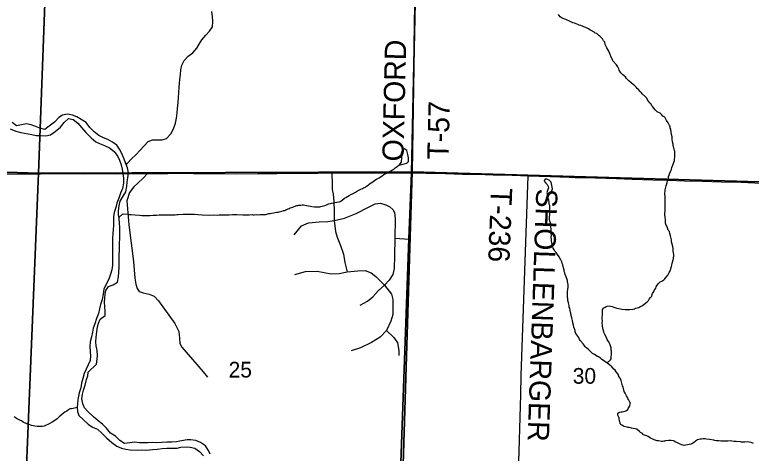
# Model space of a CAD drawing. Extents: x 0 to 34, y 0 to 22.
# Drawn here: x 5.004 to 6.971, y 18.962 to 20.132 of the extents above; entities that cross this region are included whole.
import ezdxf

# ---------------------------------------------------------------- set-up
doc = ezdxf.new("R2010")
doc.units = 0
for name, color, linetype in [('Default', 7, 'Continuous'), ('GM_X_Major_River', 7, 'Continuous'), ('GM_X_Minor_River', 7, 'Continuous'), ('GM_X_Section', 7, 'Continuous'), ('GM_X_Section_Text', 7, 'Continuous'), ('GM_X_State_Route', 7, 'Continuous'), ('GM_X_Township_Road', 7, 'Continuous'), ('GM_X_Township_Road_Text', 7, 'Continuous')]:
    doc.layers.add(name, color=color, linetype=linetype)

msp = doc.modelspace()

# ---------------------------------------------------------------- linework, layer by layer
at = {"layer": 'Default'}
msp.add_lwpolyline([(4.98, 17.7015), (5.0396, 17.6997), (5.1253, 17.6972), (5.2207, 17.6942), (5.2737, 17.6923), (5.3125, 17.691), (5.4195, 17.6873), (5.5532, 17.6849), (5.9893, 17.6676), (6.0568, 19.5343), (6.0632, 19.7108), (6.0696, 20.0002), (6.0777, 20.3704), (6.08, 20.4768), (6.0809, 20.5156), (6.0839, 20.7194), (6.0871, 20.9), (2.1, 20.9)], dxfattribs=at)
msp.add_lwpolyline([(8.9, 17.6104), (8.9, 20.9), (6.0871, 20.9), (6.0839, 20.7194), (6.0809, 20.5156), (6.08, 20.4768), (6.0777, 20.3704), (6.0696, 20.0002), (6.0632, 19.7108), (6.0568, 19.5343), (5.9893, 17.6676), (6.9889, 17.643), (7.0308, 17.6406), (8.0065, 17.6245)], close=True, dxfattribs=at)
at = {"layer": 'GM_X_Major_River'}
for points in [[(5.2835, 19.6225), (5.2857, 19.635), (5.2941, 19.648), (5.3009, 19.66), (5.3035, 19.6736), (5.3046, 19.6861), (5.3061, 19.6967), (5.3076, 19.7107), (5.3053, 19.7237), (5.2996, 19.7371), (5.2961, 19.7471), (5.2918, 19.7574), (5.2854, 19.7705), (5.277, 19.784), (5.2655, 19.7927), (5.2527, 19.7995), (5.2411, 19.804), (5.2284, 19.8101), (5.2161, 19.8195), (5.205, 19.8312), (5.1948, 19.8444), (5.1821, 19.8531), (5.1698, 19.8599), (5.1581, 19.8644), (5.1453, 19.867), (5.1315, 19.864), (5.1219, 19.8582), (5.1101, 19.846), (5.0965, 19.8349), (5.0849, 19.8262), (5.0709, 19.8296), (5.0578, 19.8349), (5.048, 19.8382), (5.0359, 19.8408), (5.0092, 19.8362), (4.9973, 19.8445)], [(4.9923, 19.8283), (5.0073, 19.8215), (5.0205, 19.8181), (5.0303, 19.8159), (5.0401, 19.8145), (5.05, 19.8127), (5.0617, 19.8105), (5.0749, 19.8097), (5.0875, 19.8094), (5.1001, 19.8117), (5.1125, 19.8208), (5.1261, 19.8326), (5.1359, 19.8449), (5.148, 19.8559), (5.1604, 19.8529), (5.1731, 19.8431), (5.183, 19.8318), (5.194, 19.8178), (5.2081, 19.8042), (5.2211, 19.7935), (5.2308, 19.7883), (5.244, 19.7838), (5.2571, 19.777), (5.2697, 19.7672), (5.2796, 19.7536), (5.2842, 19.744), (5.2888, 19.7321), (5.2915, 19.7199), (5.2931, 19.7088), (5.2943, 19.6962), (5.2947, 19.6826), (5.292, 19.6686), (5.2867, 19.6558), (5.2818, 19.6427), (5.2769, 19.6299), (5.2739, 19.6182), (5.2697, 19.6047), (5.2678, 19.5926), (5.2683, 19.5804), (5.2676, 19.5706), (5.2673, 19.5581)], [(5.2005, 19.1783), (5.2223, 19.1994), (5.2246, 19.2134), (5.2252, 19.2229), (5.2241, 19.2362), (5.2214, 19.2488), (5.2205, 19.2591), (5.2213, 19.272), (5.2236, 19.2859), (5.2254, 19.2992), (5.2276, 19.3094), (5.2321, 19.3195), (5.2453, 19.3294), (5.2456, 19.3396), (5.2448, 19.3537), (5.2444, 19.3643), (5.2447, 19.3757), (5.2457, 19.3867), (5.2475, 19.3965), (5.2543, 19.4069), (5.2669, 19.4115), (5.2789, 19.4188), (5.2812, 19.4332), (5.2819, 19.4453), (5.2831, 19.4582), (5.2834, 19.4703), (5.2833, 19.4802), (5.2832, 19.4912), (5.2836, 19.5029), (5.2844, 19.5181), (5.285, 19.5397), (5.2846, 19.553), (5.2845, 19.5652), (5.2841, 19.5758), (5.2833, 19.588), (5.2817, 19.599), (5.2816, 19.6089), (5.2835, 19.6225)], [(5.2673, 19.5581), (5.2666, 19.5486), (5.2651, 19.5357), (5.2651, 19.5217), (5.2652, 19.5122), (5.2652, 19.4989), (5.2652, 19.486), (5.2657, 19.4765), (5.2654, 19.4643), (5.2635, 19.4519), (5.2601, 19.4398), (5.2556, 19.427), (5.2484, 19.4132), (5.2419, 19.4001), (5.24, 19.3865), (5.2374, 19.3721), (5.2332, 19.3593), (5.2302, 19.3472), (5.2276, 19.3352), (5.223, 19.3213), (5.2181, 19.3073), (5.214, 19.2961), (5.2122, 19.2855), (5.2091, 19.2723), (5.2057, 19.2595), (5.2046, 19.2466), (5.2058, 19.2337), (5.2069, 19.2215), (5.2059, 19.2097), (5.1894, 19.1747)], [(5.1894, 19.1747), (5.1858, 19.1614), (5.1829, 19.1493), (5.1807, 19.1364), (5.1767, 19.1236), (5.1738, 19.1096), (5.172, 19.0956), (5.1714, 19.0838), (5.1716, 19.0732), (5.1756, 19.0625), (5.1875, 19.0509), (5.2002, 19.0393), (5.2122, 19.0318), (5.225, 19.0259), (5.237, 19.0158), (5.2504, 19.0023), (5.2635, 18.9907), (5.2773, 18.9805), (5.2897, 18.9758), (5.3011, 18.9729), (5.3124, 18.9708), (5.3322, 18.9705), (5.342, 18.9707), (5.3542, 18.9705), (5.3637, 18.9707), (5.3732, 18.9716), (5.3849, 18.973), (5.3979, 18.9746), (5.41, 18.9752), (5.4233, 18.9753), (5.4381, 18.9758), (5.448, 18.9783), (5.4629, 18.9792), (5.4727, 18.9779), (5.4848, 18.9754), (5.4975, 18.9668), (5.5083, 18.9552)], [(5.5259, 18.9595), (5.5219, 18.9694), (5.5134, 18.9817), (5.5003, 18.991), (5.4878, 18.9962), (5.4738, 18.9976), (5.4643, 18.9974), (5.4495, 18.9946), (5.4365, 18.9925), (5.4236, 18.9916), (5.4107, 18.9919), (5.3967, 18.991), (5.3837, 18.9901), (5.3716, 18.9903), (5.3587, 18.9901), (5.3492, 18.9899), (5.3371, 18.9897), (5.3238, 18.9911), (5.3116, 18.9894), (5.2972, 18.9878), (5.2848, 18.996), (5.2729, 19.0072), (5.2601, 19.0158), (5.2497, 19.0289), (5.2389, 19.0397), (5.2269, 19.0487), (5.2142, 19.0595), (5.2004, 19.0723), (5.1908, 19.0835), (5.186, 19.0934), (5.1836, 19.1072), (5.1854, 19.1197), (5.1878, 19.1299), (5.1923, 19.1438), (5.1963, 19.1586), (5.1999, 19.1684), (5.2005, 19.1783)]]:
    msp.add_lwpolyline(points, dxfattribs=at)
at = {"layer": 'GM_X_Minor_River'}
for points in [[(5.3017, 19.7321), (5.3056, 19.7358), (5.3159, 19.7477), (5.3272, 19.7587), (5.3389, 19.7709), (5.3495, 19.7828), (5.3604, 19.7939), (5.3723, 19.7985), (5.3853, 19.7989), (5.3978, 19.7985), (5.4097, 19.8024), (5.421, 19.8142), (5.4282, 19.8281), (5.4336, 19.8431), (5.4362, 19.8567), (5.4378, 19.8703), (5.4389, 19.8824), (5.4404, 19.8984), (5.4412, 19.9105), (5.4423, 19.9253), (5.4431, 19.9389), (5.4445, 19.9491), (5.4452, 19.9597), (5.4467, 19.9733), (5.4478, 19.9851), (5.4508, 19.9979), (5.4565, 20.0099), (5.4675, 20.0221), (5.4802, 20.0305), (5.4904, 20.0431), (5.4965, 20.0543), (5.5036, 20.0652), (5.5146, 20.0778), (5.5244, 20.0889), (5.5323, 20.1001), (5.5331, 20.1148), (5.5319, 20.1278), (5.5308, 20.1411)], [(6.4986, 20.1096), (6.494, 20.1105), (6.491, 20.1125), (6.4873, 20.1145), (6.4756, 20.1195), (6.4655, 20.1236), (6.4606, 20.1269), (6.4581, 20.1304), (6.4555, 20.1328)], [(6.7401, 19.5972), (6.7406, 19.6124), (6.7404, 19.617), (6.7408, 19.6296), (6.7407, 19.638), (6.7404, 19.641), (6.7406, 19.646), (6.7401, 19.654), (6.7402, 19.6567), (6.7407, 19.6608), (6.7408, 19.6654), (6.7435, 19.6756), (6.7439, 19.6786), (6.7456, 19.6839), (6.747, 19.6911), (6.7495, 19.6963), (6.7497, 19.7009), (6.7513, 19.7035), (6.7526, 19.708), (6.7559, 19.7156), (6.7575, 19.7189), (6.7588, 19.7246), (6.7609, 19.7306), (6.7652, 19.7438), (6.7657, 19.7472), (6.7662, 19.7522), (6.7668, 19.7579), (6.7666, 19.7617), (6.7664, 19.767), (6.7653, 19.7697), (6.7647, 19.7735), (6.7636, 19.7766), (6.762, 19.7839), (6.7617, 19.787), (6.7604, 19.7931), (6.7595, 19.8004), (6.7593, 19.8061), (6.758, 19.8126), (6.757, 19.8188), (6.7558, 19.8272), (6.7543, 19.8299), (6.7537, 19.8337), (6.7527, 19.8368), (6.7491, 19.8438), (6.7443, 19.8504), (6.7397, 19.8586), (6.7348, 19.8614), (6.7311, 19.8658), (6.7271, 19.8697), (6.7195, 19.873), (6.7136, 19.8785), (6.7082, 19.8867), (6.7052, 19.8891), (6.7031, 19.8934), (6.7005, 19.8965), (6.6942, 19.9032), (6.6914, 19.9098), (6.6881, 19.9133), (6.6792, 19.9209), (6.6777, 19.9236), (6.6752, 19.9271), (6.6689, 19.9334), (6.6659, 19.9354), (6.6634, 19.9389), (6.6601, 19.9429), (6.6504, 19.9501), (6.6437, 19.9564), (6.6378, 19.9619), (6.6346, 19.9666), (6.6319, 19.9686), (6.6267, 19.9726), (6.6227, 19.9777), (6.6176, 19.9847), (6.6166, 19.9878), (6.6141, 19.9936), (6.6104, 19.9987), (6.6013, 20.0096), (6.6002, 20.0131), (6.5962, 20.019), (6.5942, 20.0259), (6.5907, 20.0355), (6.5853, 20.0445), (6.5802, 20.053), (6.5797, 20.0592), (6.576, 20.0631), (6.5731, 20.0681), (6.5672, 20.0744), (6.5646, 20.0761), (6.5579, 20.082), (6.5542, 20.0837), (6.5508, 20.0857), (6.5433, 20.0901), (6.5392, 20.0918), (6.5358, 20.0946), (6.5287, 20.0982), (6.5253, 20.0991), (6.5219, 20.1011), (6.5152, 20.1037), (6.511, 20.1046), (6.5072, 20.1066), (6.4986, 20.1096)], [(6.0293, 19.7309), (6.0511, 19.7358), (6.0558, 19.7409), (6.0557, 19.7501), (6.054, 19.7596), (6.0513, 19.7699), (6.0446, 19.7743), (6.0395, 19.7714)], [(6.0395, 19.7714), (6.0355, 19.7616), (6.0367, 19.751), (6.0356, 19.7388), (6.0293, 19.7309)], [(5.8728, 19.6338), (5.8774, 19.6367), (5.8845, 19.6426), (5.888, 19.6447), (5.8923, 19.6473), (5.8973, 19.6501), (5.9035, 19.6533), (5.9062, 19.6544), (5.914, 19.6587), (5.9191, 19.6623), (5.9284, 19.667), (5.9323, 19.6684), (5.9354, 19.6702), (5.9404, 19.6723), (5.9435, 19.6745), (5.9475, 19.6777), (5.951, 19.6807), (5.9557, 19.6836), (5.9604, 19.6868), (5.9654, 19.6908), (5.9697, 19.6934), (5.9775, 19.6973), (5.9806, 19.6998), (5.9853, 19.7027), (5.99, 19.706), (5.997, 19.7096), (6.0009, 19.7125), (6.0079, 19.7157), (6.011, 19.7175), (6.0145, 19.7193), (6.0172, 19.7207), (6.0203, 19.7236), (6.0254, 19.7276), (6.0293, 19.7309)], [(6.4227, 19.6946), (6.4197, 19.6926), (6.4177, 19.6885), (6.4225, 19.683), (6.4258, 19.6795), (6.4283, 19.6741), (6.4294, 19.6703), (6.4274, 19.6662), (6.4252, 19.6583), (6.4264, 19.6514)], [(6.4264, 19.6514), (6.4362, 19.658), (6.4395, 19.6674), (6.4363, 19.6857), (6.4311, 19.6912), (6.4221, 19.6948)], [(6.4308, 19.6322), (6.4298, 19.6376), (6.4284, 19.6426), (6.4278, 19.6475), (6.4264, 19.6514)], [(5.2827, 19.5921), (5.2922, 19.6005), (5.2957, 19.6007), (5.3064, 19.6004), (5.3109, 19.5994), (5.3155, 19.5989), (5.3246, 19.5982), (5.3371, 19.597), (5.3432, 19.5968), (5.3562, 19.5964), (5.3646, 19.5968), (5.3741, 19.5973), (5.3829, 19.5977), (5.3898, 19.5979), (5.3955, 19.5984), (5.4104, 19.5983), (5.4165, 19.5985), (5.4219, 19.5987), (5.4326, 19.5987), (5.4368, 19.5989), (5.4406, 19.5995), (5.4543, 19.6002), (5.4582, 19.6005), (5.4742, 19.5999), (5.4845, 19.5999), (5.4932, 19.5996), (5.505, 19.5985), (5.5252, 19.5978), (5.5344, 19.5982), (5.5454, 19.5978), (5.5504, 19.5981), (5.5554, 19.5983), (5.568, 19.5986), (5.5725, 19.5984), (5.5764, 19.5987), (5.5855, 19.5991), (5.5886, 19.599), (5.5974, 19.5991), (5.6134, 19.5986), (5.6225, 19.5986), (5.6263, 19.5985), (5.6305, 19.5987), (5.6382, 19.5988), (5.6412, 19.5987), (5.6439, 19.5986), (5.6488, 19.5989), (5.653, 19.5987), (5.6588, 19.5989), (5.6614, 19.5988), (5.6645, 19.5991), (5.6714, 19.5992), (5.6744, 19.5995), (5.6829, 19.6015), (5.6863, 19.6021), (5.6894, 19.6032), (5.6955, 19.6041), (5.6994, 19.6047), (5.7028, 19.6054), (5.7074, 19.6056), (5.7101, 19.6063), (5.7178, 19.6083), (5.7217, 19.6097), (5.7251, 19.6103), (5.7279, 19.6121), (5.7344, 19.6146), (5.7371, 19.6156), (5.7398, 19.6171), (5.7468, 19.6187), (5.7503, 19.6209), (5.7572, 19.6229), (5.7603, 19.6236), (5.763, 19.6243), (5.7679, 19.6245), (5.7714, 19.6247), (5.7752, 19.625), (5.779, 19.6245), (5.7835, 19.6236), (5.7885, 19.6226), (5.7941, 19.6213), (5.7972, 19.6208), (5.8048, 19.6198), (5.8097, 19.6196), (5.8158, 19.6198), (5.8189, 19.6201), (5.8216, 19.6207), (5.8285, 19.6224), (5.8324, 19.6234), (5.837, 19.6252), (5.842, 19.6276), (5.8474, 19.629), (5.8501, 19.6293), (5.8551, 19.6302), (5.8585, 19.6309), (5.8639, 19.6318), (5.8701, 19.6328), (5.8728, 19.6338)], [(6.6271, 19.1419), (6.6235, 19.1562), (6.621, 19.1624), (6.6174, 19.1671), (6.6149, 19.1733), (6.6098, 19.1788), (6.6073, 19.1834), (6.6039, 19.1866), (6.5995, 19.1913), (6.597, 19.1948), (6.5943, 19.1965), (6.5869, 19.202), (6.5835, 19.2044), (6.5794, 19.2069), (6.5765, 19.2093), (6.5716, 19.2125), (6.5679, 19.2153), (6.5627, 19.2189), (6.56, 19.2201), (6.5529, 19.2245), (6.5503, 19.2265), (6.547, 19.2286), (6.5444, 19.2309), (6.5388, 19.2361), (6.5359, 19.2388), (6.5273, 19.2456), (6.5244, 19.2503), (6.5219, 19.2542), (6.5134, 19.2625), (6.5123, 19.2656), (6.5098, 19.2706), (6.5073, 19.2745), (6.5022, 19.2819), (6.5004, 19.2862), (6.5005, 19.2892), (6.4988, 19.2938), (6.4971, 19.2988), (6.4957, 19.3042), (6.494, 19.3104), (6.4931, 19.3165), (6.4914, 19.3234), (6.4901, 19.3299), (6.4888, 19.3361), (6.4881, 19.3388), (6.4875, 19.3426), (6.4858, 19.3495), (6.4847, 19.3522), (6.4841, 19.3564), (6.4824, 19.3637), (6.4811, 19.3695), (6.4805, 19.3752), (6.4802, 19.3779), (6.4804, 19.3813), (6.4802, 19.3874), (6.4804, 19.3943), (6.4809, 19.3981), (6.4816, 19.4061), (6.4818, 19.4125), (6.4811, 19.416), (6.4801, 19.4202), (6.4798, 19.4229), (6.476, 19.4325), (6.4739, 19.4391), (6.4725, 19.4433), (6.4715, 19.4475), (6.4712, 19.451), (6.4691, 19.4568), (6.4671, 19.4652), (6.4657, 19.4683), (6.4647, 19.4733), (6.4611, 19.4799), (6.4597, 19.4826), (6.4579, 19.4861), (6.4535, 19.4924), (6.4499, 19.4978), (6.4458, 19.5014), (6.444, 19.5045), (6.4415, 19.5092), (6.4395, 19.5165), (6.4379, 19.5249), (6.4372, 19.528), (6.4369, 19.5322), (6.4368, 19.5383), (6.4369, 19.5432), (6.4367, 19.5489), (6.4368, 19.552), (6.4366, 19.5562), (6.4364, 19.5611), (6.4345, 19.5719), (6.4342, 19.5757), (6.4329, 19.5811), (6.4323, 19.586), (6.432, 19.5891), (6.4321, 19.5929), (6.4327, 19.5986), (6.4324, 19.6024), (6.4328, 19.6123), (6.4327, 19.6207), (6.4324, 19.6234), (6.4313, 19.6268), (6.4308, 19.6322)], [(6.5856, 19.203), (6.5948, 19.2113), (6.5961, 19.2143), (6.5966, 19.2196), (6.5972, 19.2245), (6.5978, 19.2314), (6.5975, 19.2348), (6.5969, 19.2375), (6.5963, 19.2429), (6.5956, 19.2459), (6.5942, 19.2509), (6.5928, 19.2537), (6.5892, 19.2599), (6.5878, 19.2626), (6.5856, 19.2657), (6.5835, 19.2723), (6.5796, 19.2793), (6.5778, 19.2827), (6.5767, 19.2862), (6.5754, 19.292), (6.5734, 19.3012), (6.5735, 19.3038), (6.5729, 19.3092), (6.5732, 19.3164), (6.5729, 19.3195), (6.5734, 19.3339), (6.5735, 19.3385), (6.5737, 19.345), (6.575, 19.3491), (6.5801, 19.3516), (6.5836, 19.3538), (6.5863, 19.3548), (6.5909, 19.3554), (6.5947, 19.3546), (6.5988, 19.3537), (6.6033, 19.352), (6.6113, 19.3494), (6.6158, 19.3485), (6.6215, 19.3472), (6.6253, 19.3466), (6.634, 19.3456), (6.6424, 19.3453), (6.6466, 19.3459), (6.6543, 19.3468), (6.6585, 19.3478), (6.6612, 19.3488), (6.6701, 19.3512), (6.6728, 19.353), (6.6802, 19.3566), (6.6837, 19.3591), (6.6892, 19.3631), (6.6927, 19.3664), (6.6959, 19.3698), (6.6983, 19.3731), (6.7015, 19.3779), (6.7047, 19.3816), (6.7063, 19.3858), (6.7072, 19.3884), (6.7104, 19.3933), (6.7116, 19.3963), (6.7133, 19.3993), (6.7157, 19.403), (6.7169, 19.406), (6.719, 19.4109), (6.7226, 19.4153), (6.7277, 19.4193), (6.7315, 19.4215), (6.7343, 19.4229), (6.7374, 19.4251), (6.7401, 19.4277), (6.7437, 19.4321), (6.7477, 19.4377), (6.7518, 19.4444), (6.7534, 19.447), (6.7547, 19.4512), (6.7576, 19.4602), (6.7589, 19.4636), (6.7598, 19.4693), (6.7621, 19.4784), (6.7629, 19.4814), (6.7631, 19.4856), (6.7635, 19.4882), (6.7637, 19.492), (6.7624, 19.5016), (6.7619, 19.5077), (6.761, 19.5142), (6.7579, 19.5261), (6.7577, 19.5315), (6.7567, 19.5349), (6.755, 19.5426), (6.7529, 19.5484), (6.752, 19.5534), (6.749, 19.5573), (6.747, 19.5635), (6.7448, 19.5681), (6.7438, 19.5708), (6.742, 19.5758), (6.7417, 19.5785), (6.7412, 19.5842), (6.7403, 19.593), (6.7401, 19.5972)], [(6.915, 18.9946), (6.9081, 18.9944), (6.9055, 18.9945), (6.9028, 18.9945), (6.8933, 18.994), (6.8895, 18.9941), (6.8838, 18.9946), (6.8804, 18.9947), (6.8777, 18.9951), (6.8736, 18.996), (6.8709, 18.9968), (6.8588, 18.9986), (6.8508, 18.9992), (6.8474, 19.0001), (6.8417, 19.0002), (6.8379, 18.9995), (6.8341, 18.9993), (6.8268, 18.9979), (6.8245, 18.9961), (6.8214, 18.9939), (6.8187, 18.9913), (6.8148, 18.9891), (6.8117, 18.9869), (6.8094, 18.9858), (6.8003, 18.9845), (6.7957, 18.9835), (6.7915, 18.9828), (6.7888, 18.9833), (6.7847, 18.9841), (6.7809, 18.9858), (6.7734, 18.9897), (6.7696, 18.9917), (6.7647, 18.9938), (6.7625, 18.9946), (6.7568, 18.9958), (6.75, 18.996), (6.742, 18.9951), (6.7397, 18.9944), (6.7374, 18.994), (6.7335, 18.9934), (6.7313, 18.9934), (6.7226, 18.9948), (6.7195, 18.9952), (6.7116, 18.9973), (6.7093, 18.9985), (6.706, 19.0005), (6.7014, 19.0025), (6.6954, 19.0065), (6.6917, 19.0081), (6.6883, 19.0089), (6.683, 19.0113), (6.68, 19.0145), (6.6748, 19.0176), (6.6726, 19.02), (6.6651, 19.0258), (6.6606, 19.0271), (6.6511, 19.0292), (6.6481, 19.0301), (6.6443, 19.0309), (6.6416, 19.0306), (6.639, 19.0314), (6.6314, 19.0331), (6.6292, 19.0343), (6.625, 19.0367), (6.6228, 19.0379), (6.6206, 19.0406), (6.6202, 19.0437), (6.6192, 19.0479), (6.6182, 19.0543), (6.6179, 19.0566), (6.6146, 19.0639), (6.6139, 19.0666), (6.6144, 19.0689), (6.6174, 19.0707), (6.6201, 19.0718), (6.6228, 19.0725), (6.6255, 19.0724), (6.6297, 19.0731), (6.6335, 19.0745), (6.6374, 19.0763), (6.6408, 19.0785), (6.642, 19.0811), (6.644, 19.0837), (6.6452, 19.0867), (6.646, 19.0894), (6.6473, 19.0931), (6.6481, 19.0954), (6.6466, 19.0985), (6.643, 19.1054), (6.6411, 19.1081), (6.6389, 19.1123), (6.6379, 19.115), (6.6361, 19.1189), (6.6335, 19.1223), (6.6309, 19.1266), (6.6303, 19.1312), (6.6296, 19.1334), (6.6282, 19.1388), (6.6271, 19.1419)], [(5.1714, 19.0838), (5.157, 19.0807), (5.1543, 19.0812), (5.1501, 19.0798), (5.1478, 19.0779), (5.1435, 19.0746), (5.1385, 19.0713), (5.1335, 19.0677), (5.1284, 19.0636), (5.123, 19.0588), (5.1172, 19.054), (5.111, 19.0496), (5.1044, 19.0452), (5.0979, 19.0412), (5.0928, 19.0383), (5.0879, 19.0365), (5.0829, 19.0343), (5.0775, 19.0333), (5.0688, 19.0332), (5.0646, 19.0333), (5.0578, 19.0342), (5.0536, 19.0355), (5.0487, 19.0363), (5.0408, 19.0396), (5.037, 19.0408), (5.0265, 19.0452), (5.022, 19.048), (5.0193, 19.0496), (5.0092, 19.0544), (5.0054, 19.0572), (5.0028, 19.0591)], [(6.9764, 18.9881), (6.9704, 18.9902), (6.9647, 18.9915), (6.9606, 18.992), (6.953, 18.9918), (6.9507, 18.9918), (6.9469, 18.9915), (6.9446, 18.9916), (6.9419, 18.992), (6.9302, 18.9931), (6.9252, 18.9936), (6.9188, 18.9945), (6.915, 18.9946)]]:
    msp.add_lwpolyline(points, dxfattribs=at)
at = {"layer": 'GM_X_Section'}
for points in [[(5.1049, 20.7104), (5.0674, 19.7096), (4.0623, 19.7415), (4.105, 20.7535)], [(6.0815, 20.7216), (6.0653, 19.7127), (5.0674, 19.7096), (5.1049, 20.7104)], [(6.0815, 20.7216), (7.0125, 20.7168), (6.9929, 19.6861), (6.0653, 19.7127)], [(4.0623, 19.7415), (5.0674, 19.7096), (5.0264, 18.7096), (4.0218, 18.7461)], [(6.0653, 19.7127), (6.0336, 18.6715), (5.0264, 18.7096), (5.0674, 19.7096)], [(6.9929, 19.6861), (7.008, 18.6577), (6.0336, 18.6715), (6.0653, 19.7127)]]:
    msp.add_lwpolyline(points, close=True, dxfattribs=at)
at = {"layer": 'GM_X_State_Route'}
msp.add_line((6.3336, 19.7038), (6.374, 19.7027), dxfattribs=at)
for points in [[(4.8861, 19.7087), (4.9141, 19.7079), (4.9476, 19.7074), (4.976, 19.7077), (5.0025, 19.7082), (5.029, 19.7079), (5.0731, 19.7082), (5.1248, 19.7083), (5.1888, 19.7082), (5.232, 19.7085), (5.2378, 19.7085)], [(5.2378, 19.7085), (5.2526, 19.7083), (5.2731, 19.7082), (5.291, 19.7083), (5.3115, 19.7086), (5.3185, 19.7086)], [(5.3185, 19.7086), (5.3423, 19.7085), (5.3587, 19.709), (5.3947, 19.7082), (5.4317, 19.7093), (5.4818, 19.709), (5.5313, 19.7084), (5.5528, 19.7084), (5.5598, 19.7084)], [(5.5598, 19.7084), (5.5935, 19.7081), (5.6524, 19.7083), (5.704, 19.7087), (5.7524, 19.7093), (5.8133, 19.7095), (5.8511, 19.7101), (5.9088, 19.7101), (5.9561, 19.7097), (5.995, 19.7102), (6.0458, 19.7101), (6.0635, 19.7103)], [(6.0635, 19.7103), (6.1024, 19.7097), (6.1332, 19.7092)], [(6.1332, 19.7092), (6.1341, 19.7092), (6.154, 19.7085), (6.1998, 19.707), (6.2344, 19.707), (6.2605, 19.7063), (6.2817, 19.7052), (6.3326, 19.7038), (6.3336, 19.7038)], [(6.374, 19.7027), (6.435, 19.7009), (6.4842, 19.699)], [(6.4842, 19.699), (6.5002, 19.6984), (6.5545, 19.6969), (6.6107, 19.6949), (6.6528, 19.6936), (6.7078, 19.6919), (6.7497, 19.6905), (6.7922, 19.6895), (6.8398, 19.6882), (6.8912, 19.6867), (6.9429, 19.6851), (6.9988, 19.6828)]]:
    msp.add_lwpolyline(points, dxfattribs=at)
at = {"layer": 'GM_X_Township_Road'}
msp.add_line((6.0192, 19.5357), (6.0571, 19.5338), dxfattribs=at)
for points in [[(6.0635, 19.7103), (6.0698, 19.9997), (6.0746, 20.2192)], [(5.3587, 19.709), (5.3473, 19.6963), (5.3338, 19.6835), (5.3219, 19.673), (5.3104, 19.6582), (5.3036, 19.6356), (5.3092, 19.5716), (5.321, 19.4737), (5.3247, 19.4289), (5.3277, 19.413), (5.3308, 19.4013), (5.3361, 19.3938), (5.3471, 19.3897), (5.3631, 19.3866), (5.3768, 19.3808), (5.3885, 19.3686), (5.4315, 19.3086), (5.4422, 19.2865), (5.444, 19.2687), (5.4453, 19.2553), (5.4506, 19.2449), (5.5073, 19.1795), (5.5185, 19.165)], [(5.8511, 19.7101), (5.8513, 19.6793), (5.8516, 19.6656), (5.8543, 19.6533), (5.8564, 19.6335), (5.8571, 19.6082), (5.8571, 19.5966), (5.8569, 19.5831), (5.8606, 19.5537), (5.8655, 19.5391), (5.8743, 19.5164), (5.8817, 19.4937), (5.8859, 19.4715), (5.8915, 19.4458)], [(6.374, 19.7027), (6.3556, 19.1693), (6.3545, 19.1185), (6.3509, 18.9967), (6.3479, 18.9106), (6.3388, 18.6893), (6.3382, 18.6726), (6.3398, 18.661), (6.3498, 18.6612)], [(5.7499, 19.5449), (5.7702, 19.5688), (5.7888, 19.5767), (5.8166, 19.58), (5.8402, 19.5809), (5.8569, 19.5831), (5.8846, 19.5898), (5.9155, 19.6021), (5.9486, 19.6185), (5.9665, 19.6273), (5.9806, 19.6293), (5.995, 19.6253), (6.0058, 19.62), (6.0135, 19.6127), (6.0177, 19.6043), (6.0195, 19.588), (6.0192, 19.5357), (6.0179, 19.4888), (6.017, 19.4548), (6.0136, 19.4387), (6.0036, 19.4239), (5.9911, 19.4102)], [(5.7518, 19.4394), (5.7806, 19.4472), (5.8119, 19.4483), (5.8494, 19.4411), (5.8705, 19.4415), (5.8915, 19.4458), (5.9199, 19.4488), (5.9402, 19.4493), (5.9554, 19.4436), (5.9686, 19.434), (5.9911, 19.4102), (6.0099, 19.3868), (6.0136, 19.3724), (6.0136, 19.3319), (6.0087, 19.3142), (5.997, 19.2894), (5.9803, 19.2721), (5.9565, 19.2576), (5.927, 19.2437), (5.9025, 19.2353)], [(5.9261, 19.3576), (5.9463, 19.3683), (5.9606, 19.3792), (5.9742, 19.3955), (5.9911, 19.4102)], [(5.997, 19.2894), (6.0167, 19.271), (6.0258, 19.257), (6.0293, 19.2364), (6.0293, 19.2228)]]:
    msp.add_lwpolyline(points, dxfattribs=at)

# ---------------------------------------------------------------- texts
at = {"layer": 'GM_X_Section_Text'}
for s, p in [('25', (5.5753, 19.1641)), ('30', (6.494, 19.1475))]:
    msp.add_text(s, height=0.04186, rotation=0, dxfattribs=at).set_placement(p)
at = {"layer": 'GM_X_Township_Road_Text'}
for s, height, rotation, p in [('OXFORD', 0.05682, 88.6638, (6.0421, 19.7404)), ('T-57', 0.05682, 88.5854, (6.1621, 19.745)), ('T-236', 0.05682, 267.7542, (6.2759, 19.6713)), ('SHOLLENBARGER', 0.056818, 268.0135, (6.3968, 19.669))]:
    msp.add_text(s, height=height, rotation=rotation, dxfattribs=at).set_placement(p)

doc.saveas('drawing.dxf')
